// Mitsubishi GX Works2 project: FX-3U汞灯读取数据   PLC: FX3U/FX3UC

PROGRAM MAIN
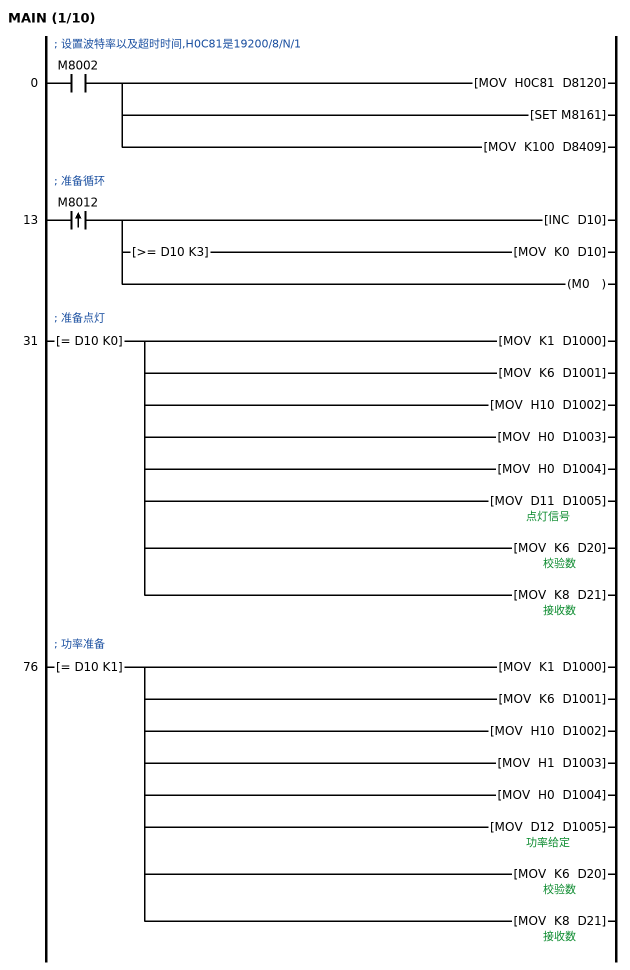
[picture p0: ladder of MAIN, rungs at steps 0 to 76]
; 设置波特率以及超时时间,H0C81是19200/8/N/1
0     LD      M8002
      MOV     H0C81 D8120
      SET     M8161
      MOV     K100 D8409
; 准备循环
13    LDP     M8012
      INC     D10
      MPS
      AND>=   D10 K3
      MOV     K0 D10
      MPP
      OUT     M0
; 准备点灯
31    LD=     D10 K0
      MOV     K1 D1000
      MOV     K6 D1001
      MOV     H10 D1002
      MOV     H0 D1003
      MOV     H0 D1004
      MOV     D11 D1005  ; 点灯信号
      MOV     K6 D20  ; 校验数
      MOV     K8 D21  ; 接收数
; 功率准备
76    LD=     D10 K1
      MOV     K1 D1000
      MOV     K6 D1001
      MOV     H10 D1002
      MOV     H1 D1003
      MOV     H0 D1004
      MOV     D12 D1005  ; 功率给定
      MOV     K6 D20
      MOV     K8 D21
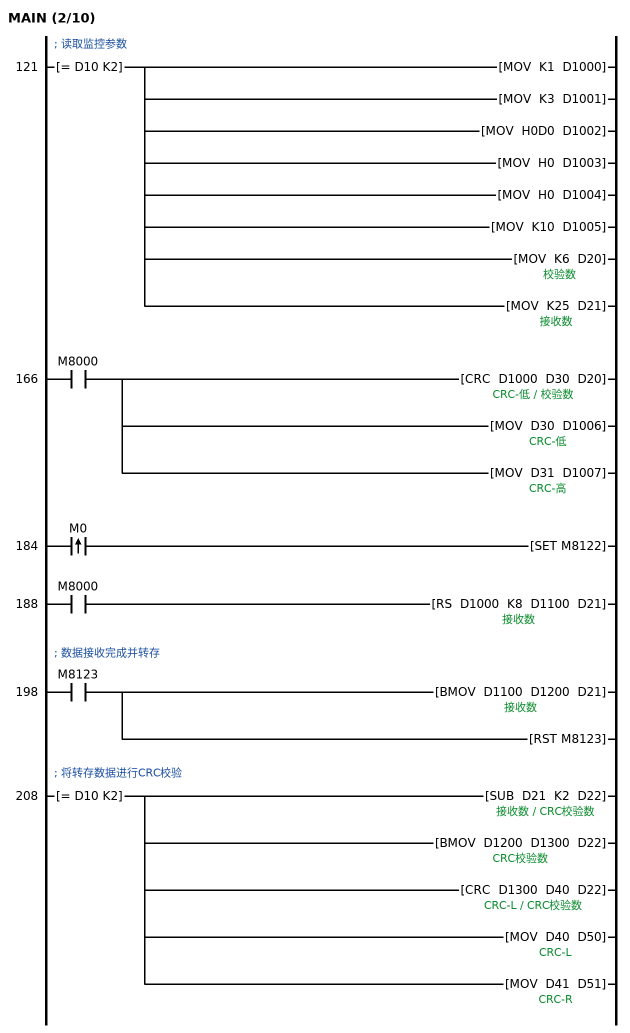
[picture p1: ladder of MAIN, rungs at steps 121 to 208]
; 读取监控参数
121   LD=     D10 K2
      MOV     K1 D1000
      MOV     K3 D1001
      MOV     H0D0 D1002
      MOV     H0 D1003
      MOV     H0 D1004
      MOV     K10 D1005
      MOV     K6 D20
      MOV     K25 D21
166   LD      M8000
      CRC     D1000 D30 D20  ; CRC-低
      MOV     D30 D1006
      MOV     D31 D1007  ; CRC-高
184   LDP     M0
      SET     M8122
188   LD      M8000
      RS      D1000 K8 D1100 D21  ; 接收数
; 数据接收完成并转存
198   LD      M8123
      BMOV    D1100 D1200 D21
      RST     M8123
; 将转存数据进行CRC校验
208   LD=     D10 K2
      SUB     D21 K2 D22  ; CRC校验数
      BMOV    D1200 D1300 D22
      CRC     D1300 D40 D22  ; CRC-L
      MOV     D40 D50
      MOV     D41 D51  ; CRC-R
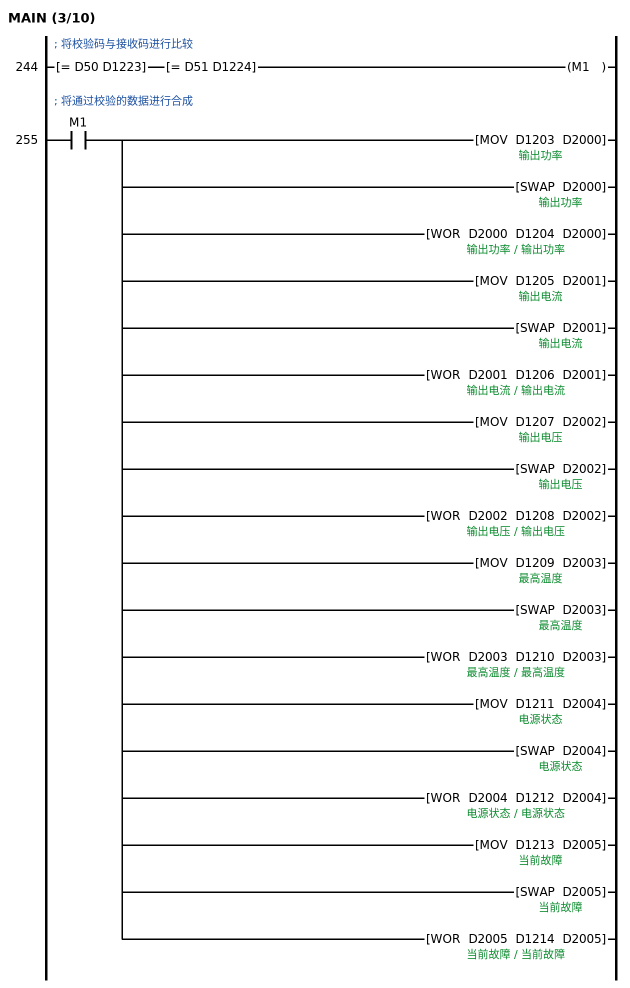
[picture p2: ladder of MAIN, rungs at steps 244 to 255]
; 将校验码与接收码进行比较
244   LD=     D50 D1223
      AND=    D51 D1224
      OUT     M1
; 将通过校验的数据进行合成
255   LD      M1
      MOV     D1203 D2000  ; 输出功率
      SWAP    D2000
      WOR     D2000 D1204 D2000
      MOV     D1205 D2001  ; 输出电流
      SWAP    D2001
      WOR     D2001 D1206 D2001
      MOV     D1207 D2002  ; 输出电压
      SWAP    D2002
      WOR     D2002 D1208 D2002
      MOV     D1209 D2003  ; 最高温度
      SWAP    D2003
      WOR     D2003 D1210 D2003
      MOV     D1211 D2004  ; 电源状态
      SWAP    D2004
      WOR     D2004 D1212 D2004
      MOV     D1213 D2005  ; 当前故障
      SWAP    D2005
      WOR     D2005 D1214 D2005
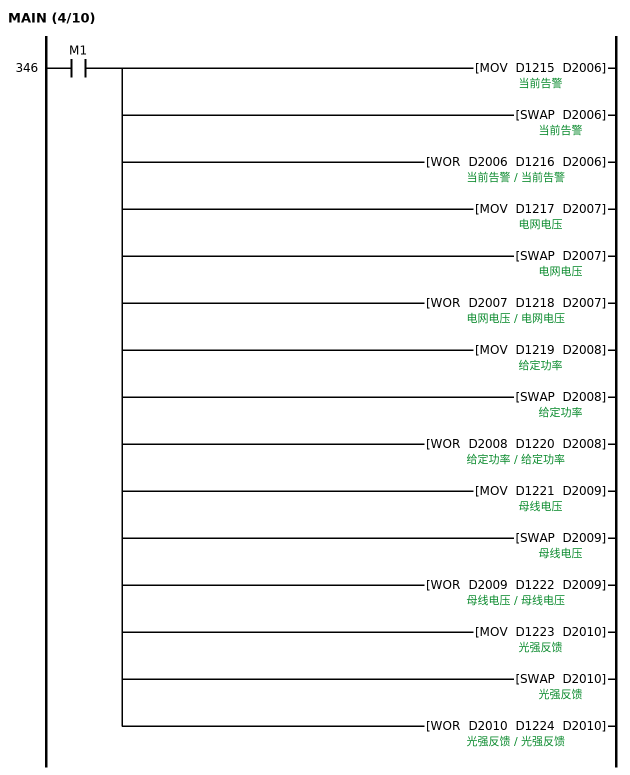
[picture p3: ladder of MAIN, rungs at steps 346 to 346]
346   LD      M1
      MOV     D1215 D2006  ; 当前告警
      SWAP    D2006
      WOR     D2006 D1216 D2006
      MOV     D1217 D2007  ; 电网电压
      SWAP    D2007
      WOR     D2007 D1218 D2007
      MOV     D1219 D2008  ; 给定功率
      SWAP    D2008
      WOR     D2008 D1220 D2008
      MOV     D1221 D2009  ; 母线电压
      SWAP    D2009
      WOR     D2009 D1222 D2009
      MOV     D1223 D2010  ; 光强反馈
      SWAP    D2010
      WOR     D2010 D1224 D2010
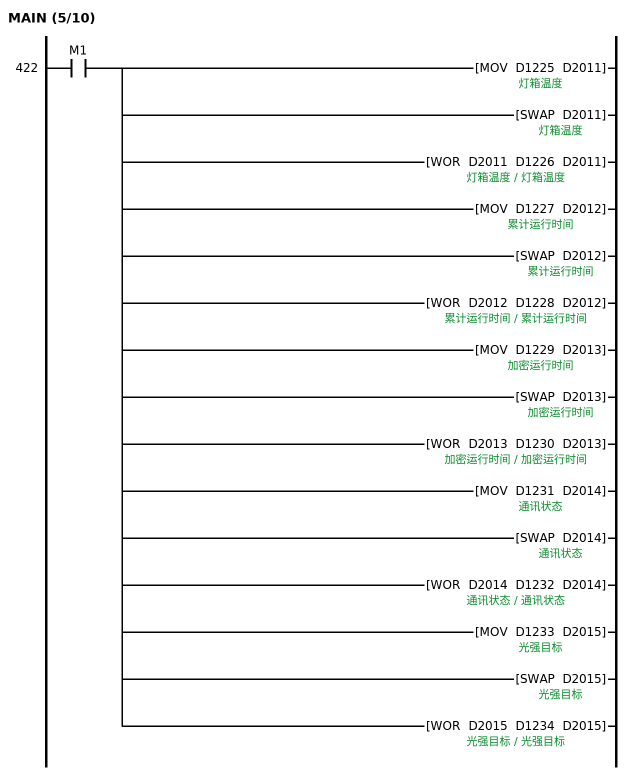
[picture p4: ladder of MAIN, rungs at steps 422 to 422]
422   LD      M1
      MOV     D1225 D2011  ; 灯箱温度
      SWAP    D2011
      WOR     D2011 D1226 D2011
      MOV     D1227 D2012  ; 累计运行时间
      SWAP    D2012
      WOR     D2012 D1228 D2012
      MOV     D1229 D2013  ; 加密运行时间
      SWAP    D2013
      WOR     D2013 D1230 D2013
      MOV     D1231 D2014  ; 通讯状态
      SWAP    D2014
      WOR     D2014 D1232 D2014
      MOV     D1233 D2015  ; 光强目标
      SWAP    D2015
      WOR     D2015 D1234 D2015
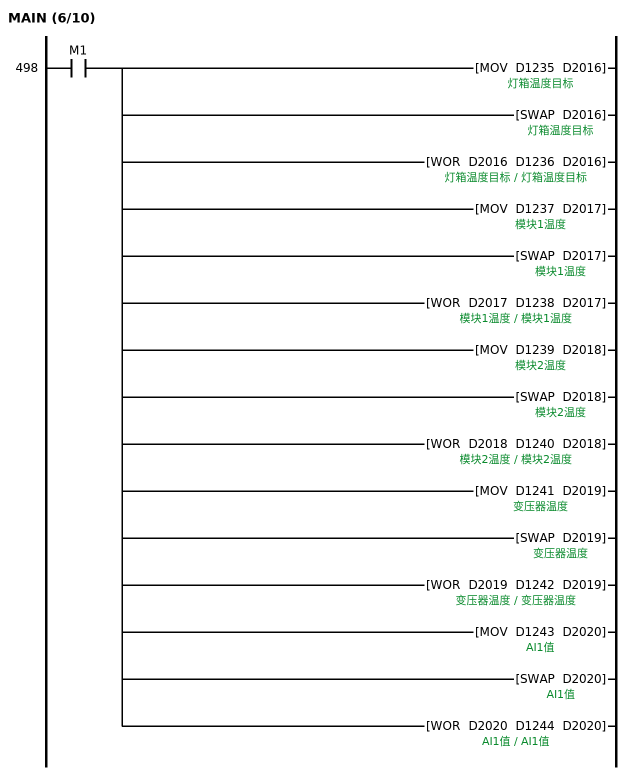
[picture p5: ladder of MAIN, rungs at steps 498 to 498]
498   LD      M1
      MOV     D1235 D2016  ; 灯箱温度目标
      SWAP    D2016
      WOR     D2016 D1236 D2016
      MOV     D1237 D2017  ; 模块1温度
      SWAP    D2017
      WOR     D2017 D1238 D2017
      MOV     D1239 D2018  ; 模块2温度
      SWAP    D2018
      WOR     D2018 D1240 D2018
      MOV     D1241 D2019  ; 变压器温度
      SWAP    D2019
      WOR     D2019 D1242 D2019
      MOV     D1243 D2020  ; AI1值
      SWAP    D2020
      WOR     D2020 D1244 D2020
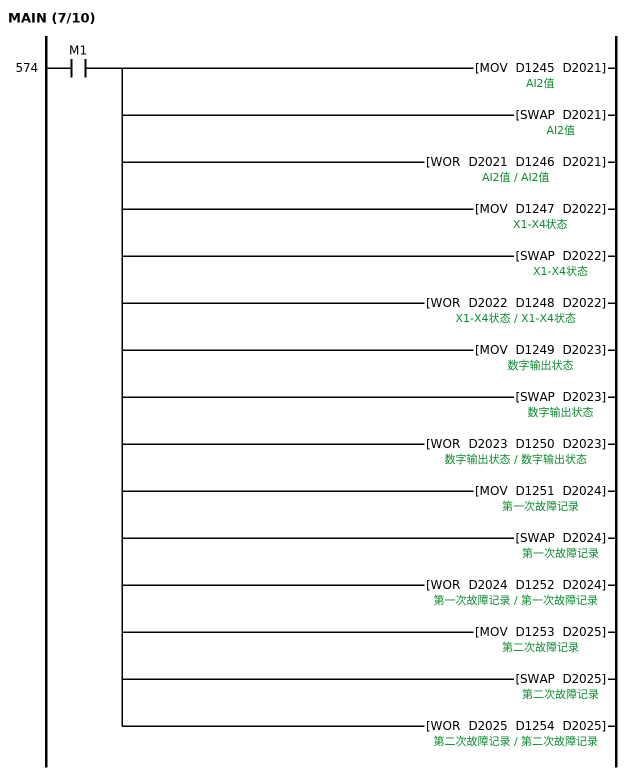
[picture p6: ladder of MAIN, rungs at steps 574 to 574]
574   LD      M1
      MOV     D1245 D2021  ; AI2值
      SWAP    D2021
      WOR     D2021 D1246 D2021
      MOV     D1247 D2022  ; X1-X4状态
      SWAP    D2022
      WOR     D2022 D1248 D2022
      MOV     D1249 D2023  ; 数字输出状态
      SWAP    D2023
      WOR     D2023 D1250 D2023
      MOV     D1251 D2024  ; 第一次故障记录
      SWAP    D2024
      WOR     D2024 D1252 D2024
      MOV     D1253 D2025  ; 第二次故障记录
      SWAP    D2025
      WOR     D2025 D1254 D2025
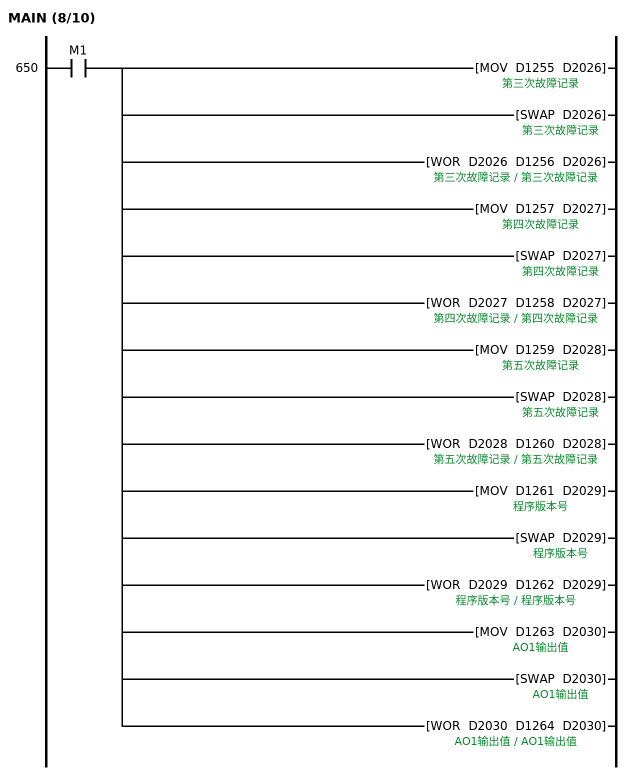
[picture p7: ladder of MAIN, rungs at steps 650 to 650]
650   LD      M1
      MOV     D1255 D2026  ; 第三次故障记录
      SWAP    D2026
      WOR     D2026 D1256 D2026
      MOV     D1257 D2027  ; 第四次故障记录
      SWAP    D2027
      WOR     D2027 D1258 D2027
      MOV     D1259 D2028  ; 第五次故障记录
      SWAP    D2028
      WOR     D2028 D1260 D2028
      MOV     D1261 D2029  ; 程序版本号
      SWAP    D2029
      WOR     D2029 D1262 D2029
      MOV     D1263 D2030  ; AO1输出值
      SWAP    D2030
      WOR     D2030 D1264 D2030
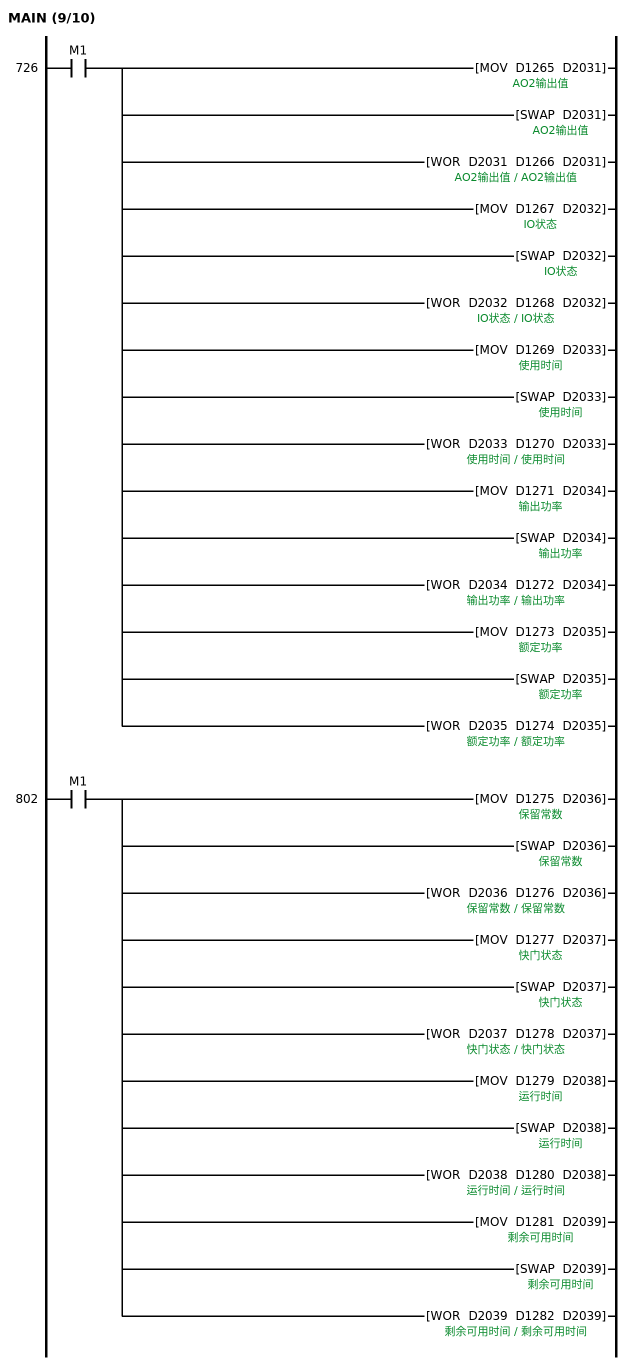
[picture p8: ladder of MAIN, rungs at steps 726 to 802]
726   LD      M1
      MOV     D1265 D2031  ; AO2输出值
      SWAP    D2031
      WOR     D2031 D1266 D2031
      MOV     D1267 D2032  ; IO状态
      SWAP    D2032
      WOR     D2032 D1268 D2032
      MOV     D1269 D2033  ; 使用时间
      SWAP    D2033
      WOR     D2033 D1270 D2033
      MOV     D1271 D2034  ; 输出功率
      SWAP    D2034
      WOR     D2034 D1272 D2034
      MOV     D1273 D2035  ; 额定功率
      SWAP    D2035
      WOR     D2035 D1274 D2035
802   LD      M1
      MOV     D1275 D2036  ; 保留常数
      SWAP    D2036
      WOR     D2036 D1276 D2036
      MOV     D1277 D2037  ; 快门状态
      SWAP    D2037
      WOR     D2037 D1278 D2037
      MOV     D1279 D2038  ; 运行时间
      SWAP    D2038
      WOR     D2038 D1280 D2038
      MOV     D1281 D2039  ; 剩余可用时间
      SWAP    D2039
      WOR     D2039 D1282 D2039
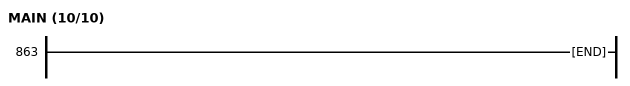
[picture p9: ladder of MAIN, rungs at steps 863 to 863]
863   END
END_PROGRAM
